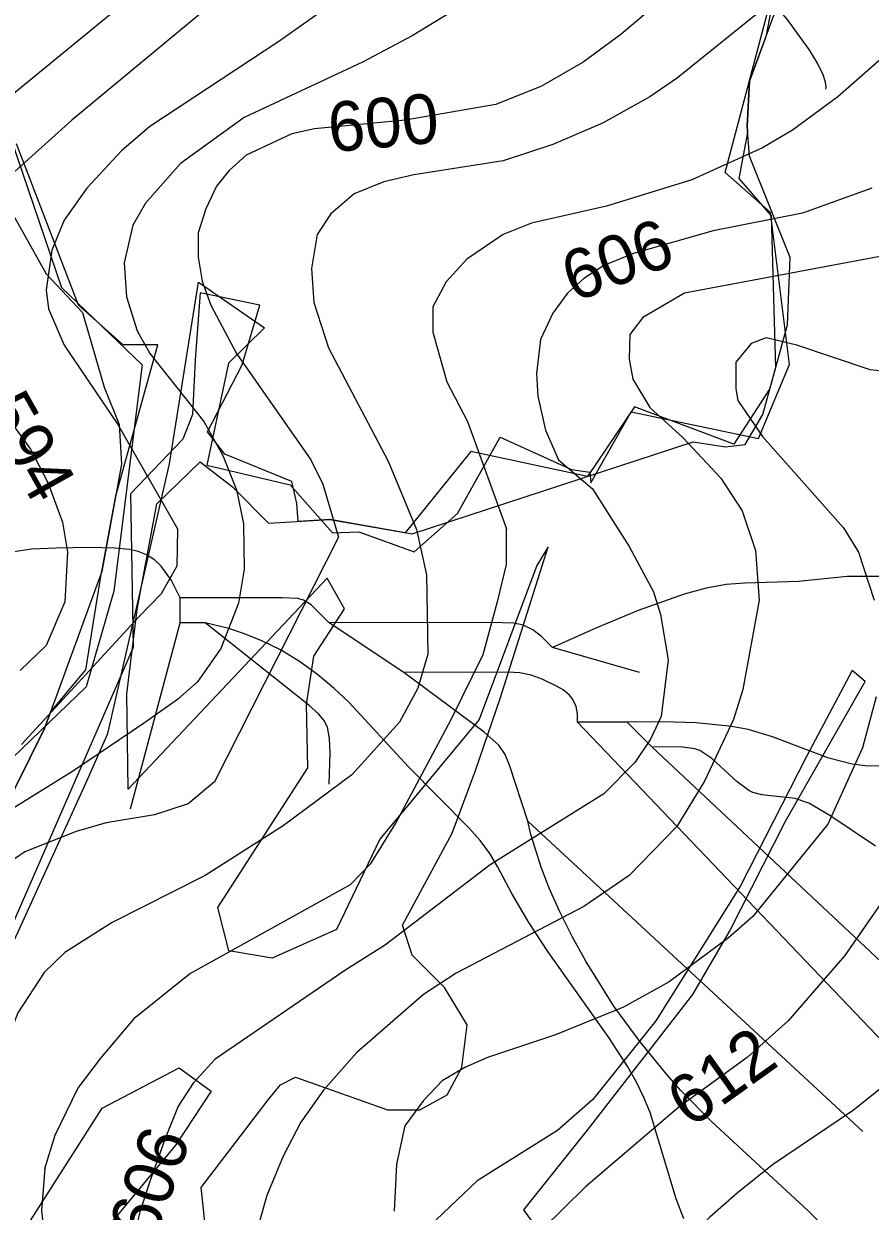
# Model space of a CAD drawing. Extents: x -709584 to -702006, y -1161789 to -1157496.
# Drawn here: x -706843.5 to -706673, y -1159575.6 to -1159336.3 of the extents above; entities that cross this region are included whole.
import ezdxf

# ---------------------------------------------------------------- set-up
doc = ezdxf.new("R2010")
doc.units = 0
for name, color, linetype in [('102_obvod PÚ', 7, 'Continuous'), ('120_vrstevnice hlavní', 7, 'Continuous'), ('121_vrstevnice hlavní_popis', 7, 'Continuous'), ('122_vrstevnice základní', 7, 'Continuous'), ('408_BPEJ_linie', 7, 'Continuous'), ('411_akumulovaný odtok', 7, 'Continuous'), ('419_LPIS PB', 7, 'Continuous')]:
    doc.layers.add(name, color=color, linetype=linetype)

msp = doc.modelspace()

# ---------------------------------------------------------------- linework, layer by layer
at = {"layer": '102_obvod PÚ'}
for points in [[(-706848.95, -1159528.57), (-706830.93, -1159489.21), (-706826.6, -1159479.29), (-706814.16, -1159424.99), (-706808.34, -1159388.37), (-706795.05, -1159397.55), (-706802.3, -1159404.68), (-706806.63, -1159425.27), (-706789.86, -1159429.21), (-706781.31, -1159438.85), (-706776, -1159438.67), (-706764.88, -1159442.72), (-706756.15, -1159434.97), (-706747.54, -1159419.57), (-706733.17, -1159426.13), (-706729.53, -1159426.67), (-706729.3, -1159428.78), (-706721.2, -1159414.52), (-706695.54, -1159419.88), (-706689.26, -1159404.94), (-706693.14, -1159374.31), (-706702.27, -1159366.26), (-706692.33, -1159328.63)], [(-706846.05, -1159359.62), (-706835.89, -1159389.45), (-706819.69, -1159405.02), (-706825.4, -1159450.65), (-706830.93, -1159469.93), (-706862.53, -1159500.28)]]:
    msp.add_lwpolyline(points, dxfattribs=at)
at = {"layer": '120_vrstevnice hlavní'}
for points in [[(-706709.12, -1159326.46), (-706723.26, -1159338.46), (-706730.83, -1159344.03), (-706739.26, -1159348.89), (-706748.41, -1159352.6), (-706766.69, -1159355.75), (-706784.98, -1159357.46), (-706789.55, -1159358.46), (-706798.7, -1159362.75), (-706802.12, -1159365.89), (-706804.7, -1159369.03), (-706806.84, -1159373.6), (-706808.41, -1159378.46), (-706808.41, -1159383.32), (-706807.55, -1159388.18), (-706805.84, -1159393.03), (-706800.7, -1159402.75), (-706785.7, -1159424.18), (-706783.27, -1159429.04), (-706780.12, -1159439.75)], [(-706661.58, -1159407.24), (-706673.06, -1159406.06), (-706687.83, -1159401.03), (-706693.98, -1159399.61), (-706696.98, -1159400.75), (-706700.12, -1159404.46), (-706700.12, -1159409.89), (-706699.69, -1159412.18), (-706694.69, -1159419.46), (-706678.4, -1159437.89), (-706675.4, -1159442.75), (-706672.26, -1159452.47)], [(-706780.12, -1159439.75), (-706805.08, -1159489.03), (-706810.37, -1159493.49), (-706817.21, -1159495.68), (-706826.92, -1159497.3), (-706832.98, -1159499.04), (-706843.27, -1159503.18), (-706853.13, -1159509.9), (-706857.13, -1159513.61), (-706860.56, -1159517.61), (-706864.27, -1159523.33), (-706866.56, -1159528.47), (-706868.13, -1159533.61), (-706872.89, -1159562.85)], [(-706671.83, -1159471.9), (-706674.55, -1159482.18), (-706681.55, -1159497.61), (-706696.69, -1159516.18), (-706701.55, -1159520.47), (-706713.55, -1159529.33), (-706722.69, -1159534.47), (-706736.41, -1159540.04), (-706750.12, -1159544.61), (-706754.69, -1159546.61), (-706759.27, -1159549.33), (-706763.02, -1159553.25), (-706766.78, -1159558.34), (-706768.46, -1159566.12), (-706768.88, -1159575.57)]]:
    msp.add_lwpolyline(points, dxfattribs=at)
msp.add_open_spline([(-706768.88, -1159575.57), (-706768.88, -1159575.58)], degree=1, dxfattribs=at)
at = {"layer": '122_vrstevnice základní'}
for points in [[(-706654.69, -1159145.74), (-706680.12, -1159166.88), (-706687.41, -1159173.59), (-706720.55, -1159207.17), (-706736.55, -1159225.17), (-706751.84, -1159244.46), (-706792.84, -1159298.46), (-706808.7, -1159317.6), (-706826.27, -1159334.6), (-706862.27, -1159364.03)], [(-706643.12, -1159157.45), (-706668.12, -1159182.59), (-706699.41, -1159216.6), (-706708.83, -1159228.74), (-706766.12, -1159293.46), (-706792.27, -1159320.32), (-706807.98, -1159334.32), (-706833.84, -1159355.75), (-706845.27, -1159366.03)], [(-706622.69, -1159158.74), (-706651.26, -1159189.31), (-706674.4, -1159215.17), (-706689.69, -1159233.74), (-706698.83, -1159246.31), (-706715.26, -1159266.74), (-706752.84, -1159307.31), (-706761.84, -1159316.17), (-706777.27, -1159329.32), (-706792.12, -1159339.89), (-706818.12, -1159357.03), (-706823.84, -1159361.89), (-706830.84, -1159369.46), (-706835.41, -1159375.89), (-706837.84, -1159381.89), (-706838.98, -1159389.89), (-706838.56, -1159393.75), (-706835.41, -1159401.03), (-706824.55, -1159417.03), (-706812.55, -1159438.04), (-706812.7, -1159445.61), (-706815.84, -1159451.18), (-706820.41, -1159455.89), (-706843.94, -1159481.51)], [(-706590.33, -1159211.59), (-706594.67, -1159221.73), (-706609.26, -1159257.6), (-706614.97, -1159269.6), (-706620.54, -1159279.31), (-706635.83, -1159302.6), (-706648.12, -1159318.17), (-706662.55, -1159335.03), (-706671.26, -1159343.75), (-706679.55, -1159351.03), (-706688.69, -1159357.75), (-706694.69, -1159361.32), (-706708.98, -1159367.75), (-706726.12, -1159373.03), (-706741.26, -1159376.46), (-706746.98, -1159378.75), (-706754.27, -1159383.75), (-706758.41, -1159388.32), (-706761.12, -1159393.32), (-706761.12, -1159398.46), (-706758.27, -1159408.46), (-706754.12, -1159416.46), (-706746.27, -1159438.04)], [(-706690.83, -1159330.17), (-706711.83, -1159347.17), (-706717.41, -1159351.03), (-706726.98, -1159356.32), (-706736.98, -1159360.6), (-706746.98, -1159363.89), (-706764.98, -1159366.75), (-706770.98, -1159368.18), (-706776.98, -1159370.6), (-706781.7, -1159374.6), (-706784.41, -1159378.75), (-706785.55, -1159385.61), (-706785.12, -1159392.46), (-706782.12, -1159401.61), (-706770.12, -1159424.46), (-706764.41, -1159438.18), (-706762.41, -1159447.32), (-706762.12, -1159463.32), (-706764.12, -1159470.18), (-706767.84, -1159477.04), (-706777.41, -1159487.61), (-706791.27, -1159497.9), (-706806.98, -1159507.9), (-706825.71, -1159517.41)], [(-706755.69, -1159332.89), (-706765.27, -1159338.75), (-706775.27, -1159344.03), (-706799.12, -1159355.18), (-706811.98, -1159364.46), (-706818.98, -1159372.46), (-706821.55, -1159376.89), (-706823.27, -1159384.46), (-706822.84, -1159391.32), (-706820.7, -1159398.18), (-706818.12, -1159402.75), (-706807.27, -1159416.46), (-706803.41, -1159423.32), (-706800.7, -1159430.18), (-706799.27, -1159437.04), (-706799.12, -1159446.18), (-706800.27, -1159453.04), (-706803.84, -1159462.18), (-706808.55, -1159468.89), (-706812.55, -1159472.47), (-706819.41, -1159477.32), (-706833.51, -1159486.8), (-706848.84, -1159496.32)], [(-706672.69, -1159369.46), (-706686.69, -1159374.46), (-706704.69, -1159378.03), (-706720.69, -1159382.6), (-706726.69, -1159385.03), (-706730.69, -1159387.61), (-706733.98, -1159390.61), (-706736.98, -1159394.61), (-706739.41, -1159399.89), (-706740.26, -1159406.75), (-706739.98, -1159411.32), (-706738.41, -1159418.18), (-706735.83, -1159424.18), (-706728.98, -1159430.03), (-706721.55, -1159441.61), (-706716.69, -1159450.75), (-706715.26, -1159455.32), (-706713.69, -1159464.47), (-706715.12, -1159475.9), (-706717.26, -1159480.47), (-706720.41, -1159485.18), (-706726.69, -1159491.47), (-706749.55, -1159505.75), (-706770.69, -1159521.9), (-706778.84, -1159527.04)], [(-706664.98, -1159382.03), (-706710.41, -1159390.61), (-706718.83, -1159395.46), (-706721.41, -1159398.89), (-706721.55, -1159403.89), (-706720.83, -1159407.89), (-706717.41, -1159413.61), (-706710.69, -1159419.75), (-706703.12, -1159427.89), (-706698.83, -1159434.46), (-706696.12, -1159442.47), (-706695.41, -1159452.47), (-706698.69, -1159470.47), (-706700.55, -1159476.47), (-706706.41, -1159488.9), (-706711.98, -1159498.04), (-706721.55, -1159507.9), (-706730.69, -1159514.18), (-706756.41, -1159527.61), (-706762.98, -1159531.9), (-706776.41, -1159543.61), (-706783.12, -1159551.18), (-706787.7, -1159557.61), (-706791.26, -1159564.49), (-706794.58, -1159572.43)], [(-706855.98, -1159403.03), (-706842.13, -1159422.03), (-706838.7, -1159428.75), (-706835.7, -1159436.75), (-706834.7, -1159442.75), (-706835.27, -1159452.75), (-706838.98, -1159461.61), (-706844.27, -1159466.61)], [(-706839.29, -1159566.96), (-706837.19, -1159560.26), (-706832.63, -1159550.81), (-706827.98, -1159544.76), (-706820.98, -1159536.47), (-706810.12, -1159527.75), (-706777.7, -1159509.75), (-706773.57, -1159505.47), (-706768.56, -1159497.39), (-706757.41, -1159476.48), (-706751, -1159463.38), (-706747.93, -1159452.23), (-706746.26, -1159445.26), (-706746.27, -1159438.04)], [(-706619.55, -1159445.89), (-706624.59, -1159454.52), (-706628.86, -1159465.05), (-706631.5, -1159477.96), (-706633.14, -1159491.38), (-706635.55, -1159502.75), (-706641.12, -1159516.75), (-706645.83, -1159525.04), (-706654.26, -1159536.18), (-706662.4, -1159544.04), (-706676.4, -1159555.18), (-706692.69, -1159566.19), (-706699.83, -1159571.9), (-706705.34, -1159576.78), (-706711.29, -1159582.62)], [(-706656.12, -1159449.89), (-706654.69, -1159462.75), (-706654.83, -1159471.9), (-706656.12, -1159481.04), (-706659.55, -1159492.47), (-706668.12, -1159509.61), (-706678.12, -1159524.04), (-706689.55, -1159537.18), (-706697.83, -1159544.61), (-706711.55, -1159554.61), (-706730.35, -1159570.68), (-706739.13, -1159579.22)], [(-706825.71, -1159517.41), (-706835.27, -1159523.47), (-706839.41, -1159527.47), (-706844.7, -1159535.61), (-706847.98, -1159544.18), (-706849.27, -1159552.76), (-706849.81, -1159565.68)], [(-706778.84, -1159527.04), (-706804.98, -1159544.9), (-706809.41, -1159549.76), (-706812.43, -1159554.39), (-706815.04, -1159560.91), (-706818.13, -1159569.55)], [(-706839.29, -1159566.96), (-706839.92, -1159575.4), (-706837.18, -1159601.02), (-706859.16, -1159631.68)], [(-706818.13, -1159569.55), (-706820.06, -1159575.49), (-706824.32, -1159592.45)], [(-706794.58, -1159572.43), (-706796.07, -1159577.85), (-706797.41, -1159586.38), (-706798.12, -1159608.68), (-706798.7, -1159622.57), (-706799.57, -1159630.23), (-706855.11, -1159702.56)]]:
    msp.add_lwpolyline(points, dxfattribs=at)
for points in [[(-706839.29, -1159566.96), (-706839.29, -1159566.96)], [(-706818.13, -1159569.55), (-706818.13, -1159569.55)], [(-706794.58, -1159572.43), (-706794.58, -1159572.43)]]:
    msp.add_open_spline(points, degree=1, dxfattribs=at)
at = {"layer": '408_BPEJ_linie'}
for points in [[(-706688.5, -1159310), (-706694.04, -1159338.95), (-706697.33, -1159347.89), (-706697.83, -1159356.93), (-706697.73, -1159358.23), (-706699.5, -1159367.5), (-706693, -1159375), (-706692.07, -1159405.61), (-706693.28, -1159409.95), (-706700.5, -1159421), (-706720.5, -1159413.5), (-706730, -1159427.5), (-706753.5, -1159422.5), (-706766.68, -1159438.86), (-706781.9, -1159436.2), (-706788.23, -1159436.56), (-706788.5, -1159433), (-706789.5, -1159428.5), (-706803, -1159423), (-706806.5, -1159418.5), (-706799.5, -1159405), (-706796, -1159393), (-706808, -1159390.5), (-706809, -1159404), (-706809.5, -1159415), (-706811.5, -1159420), (-706822, -1159431), (-706821.5, -1159462), (-706849, -1159525)], [(-706848.35, -1159496.37), (-706839.34, -1159478.29), (-706838.13, -1159474.98), (-706831, -1159466.5), (-706827.87, -1159446.78), (-706827.82, -1159446.66), (-706825, -1159431.41), (-706816.5, -1159401), (-706823.5, -1159401), (-706832.5, -1159393), (-706845, -1159360.5)]]:
    msp.add_lwpolyline(points, dxfattribs=at)
at = {"layer": '411_akumulovaný odtok'}
for p, q in [((-706811.99, -1159457), (-706811.99, -1159452)), ((-706821.99, -1159494.5), (-706811.99, -1159457)), ((-706806.99, -1159457), (-706811.99, -1159457)), ((-706766.99, -1159467), (-706781.99, -1159457)), ((-706719.49, -1159467), (-706736.99, -1159462)), ((-706721.99, -1159477), (-706731.99, -1159477)), ((-706716.99, -1159482), (-706721.99, -1159477)), ((-706674.49, -1159559.5), (-706741.99, -1159497))]:
    msp.add_line(p, q, dxfattribs=at)
for points in [[(-706681.99, -1159349.5), (-706681.87, -1159349.08), (-706682.04, -1159348.07), (-706682.53, -1159346.59), (-706683.65, -1159344.24), (-706685.3, -1159341.5), (-706689.75, -1159335.4), (-706694.89, -1159329.34), (-706701.85, -1159322.11), (-706759.36, -1159264.71), (-706768.21, -1159255.54), (-706773.08, -1159249.46), (-706775.38, -1159246.13), (-706777.41, -1159242.77), (-706780.01, -1159237.5), (-706781.54, -1159233.57), (-706781.99, -1159232)], [(-706811.99, -1159452), (-706813.74, -1159448.47), (-706815.85, -1159445.59), (-706817.19, -1159444.33), (-706818.78, -1159443.31), (-706820.46, -1159442.61), (-706822.13, -1159442.21), (-706825.34, -1159441.95), (-706830.29, -1159441.86), (-706836.97, -1159441.94), (-706841.94, -1159442.19), (-706846.79, -1159442.88), (-706855.63, -1159445.46), (-706858.64, -1159445.68), (-706861.75, -1159445.26), (-706866.46, -1159444.03), (-706886.99, -1159437)], [(-706670.53, -1159447.68), (-706677.65, -1159447.65), (-706687.48, -1159448.68), (-706698.31, -1159448.99), (-706702.01, -1159449.26), (-706706.05, -1159450.02), (-706710.48, -1159451.24), (-706719.76, -1159454.53), (-706728.3, -1159458.09), (-706736.99, -1159462)], [(-706781.99, -1159457), (-706785.63, -1159453.37), (-706787.16, -1159452.42), (-706788.32, -1159452.13), (-706791.45, -1159451.96), (-706811.99, -1159452)], [(-706781.99, -1159489.5), (-706781.82, -1159483.18), (-706781.91, -1159480.3), (-706782.34, -1159478.01), (-706783.05, -1159476.63), (-706784.14, -1159475.37), (-706786.08, -1159473.63), (-706806.99, -1159457)], [(-706710.59, -1159577.13), (-706712.08, -1159573.09), (-706717.37, -1159555.71), (-706718.6, -1159552.67), (-706720.13, -1159549.54), (-706721.86, -1159546.5), (-706725.67, -1159540.57), (-706737.93, -1159523.21), (-706741.78, -1159517.4), (-706745.23, -1159511.54), (-706748.08, -1159506.09), (-706749.65, -1159503.49), (-706751.62, -1159500.85), (-706753.85, -1159498.34), (-706766.05, -1159486.06), (-706778.01, -1159473.01), (-706780.98, -1159470.21), (-706784.35, -1159467.4), (-706788, -1159464.77), (-706791.82, -1159462.46), (-706795.54, -1159460.64), (-706799.07, -1159459.22), (-706802.19, -1159458.17), (-706806.99, -1159457)], [(-706736.99, -1159462), (-706739.23, -1159459.76), (-706740.97, -1159458.44), (-706742.93, -1159457.48), (-706744.82, -1159457.1), (-706749.41, -1159456.96), (-706781.99, -1159457)], [(-706731.99, -1159477), (-706731.99, -1159475.36), (-706732.27, -1159473.86), (-706733, -1159472.3), (-706733.57, -1159471.6), (-706734.88, -1159470.53), (-706736.24, -1159469.77), (-706739.09, -1159468.38), (-706741.29, -1159467.54), (-706743.61, -1159467.09), (-706746, -1159466.96), (-706766.99, -1159467)], [(-706741.99, -1159497), (-706745.67, -1159485.71), (-706746.58, -1159483.57), (-706747.84, -1159481.67), (-706750.8, -1159479.06), (-706766.99, -1159467)], [(-706579.49, -1159629.5), (-706583.27, -1159624.18), (-706589.17, -1159616.82), (-706592.75, -1159612.79), (-706596.59, -1159608.78), (-706600.53, -1159604.99), (-706604.42, -1159601.59), (-706608.08, -1159598.79), (-706617.81, -1159592.6), (-706620.99, -1159590.44), (-706624.32, -1159587.9), (-706630.69, -1159582.34), (-706636.82, -1159576.42), (-706648.8, -1159564.13), (-706731.99, -1159477)], [(-706589.49, -1159499.5), (-706603.81, -1159491.42), (-706612.59, -1159486.87), (-706617.42, -1159484.86), (-706619.83, -1159484.08), (-706622.29, -1159483.5), (-706624.92, -1159483.14), (-706627.58, -1159482.99), (-706633, -1159483.07), (-706641.22, -1159483.69), (-706663.23, -1159485.73), (-706668.68, -1159485.97), (-706674.05, -1159485.81), (-706676.69, -1159485.46), (-706681.33, -1159484.28), (-706692.71, -1159479.99), (-706697.59, -1159478.5), (-706700.88, -1159477.89), (-706708.06, -1159477.19), (-706714.88, -1159476.96), (-706721.99, -1159477)], [(-706671.99, -1159502), (-706681.13, -1159495.8), (-706685.4, -1159493.34), (-706688.13, -1159492.44), (-706694.87, -1159491.69), (-706696.66, -1159491.19), (-706697.5, -1159490.78), (-706699.82, -1159489.08), (-706704.93, -1159484.36), (-706707.32, -1159482.76), (-706708.33, -1159482.43), (-706710.76, -1159482.04), (-706716.99, -1159482)], [(-706524.49, -1159674.5), (-706525.18, -1159673.85), (-706526.52, -1159671.64), (-706533.03, -1159658.66), (-706535.98, -1159653.09), (-706539.31, -1159647.41), (-706542.91, -1159641.82), (-706546.62, -1159636.5), (-706550.27, -1159631.66), (-706556.98, -1159623.59), (-706563.82, -1159615.99), (-706571.08, -1159608.51), (-706578.73, -1159601.16), (-706590.47, -1159590.41), (-706602.37, -1159580.03), (-706610.42, -1159573.47), (-706618.62, -1159567.48), (-706622.8, -1159564.81), (-706630.76, -1159560.32), (-706634.59, -1159557.94), (-706638.65, -1159554.87), (-706642.57, -1159551.49), (-706657.95, -1159537.41), (-706716.99, -1159482)], [(-706679.31, -1159581.67), (-706685.54, -1159575.5), (-706704.98, -1159557.52), (-706711.16, -1159551.25), (-706714, -1159548.05), (-706719.39, -1159541.42), (-706724.65, -1159534.24), (-706730.32, -1159525.16), (-706733.06, -1159520.23), (-706735.55, -1159515.27), (-706737.69, -1159510.48), (-706739.32, -1159506.23), (-706741.41, -1159499.63), (-706741.99, -1159497)]]:
    msp.add_lwpolyline(points, dxfattribs=at)
at = {"layer": '419_LPIS PB'}
for points in [[(-706806.9, -1159578.9), (-706807.79, -1159570.82), (-706794.29, -1159553.11), (-706791.79, -1159550.09), (-706788.78, -1159548.59), (-706770.26, -1159555.11), (-706763.75, -1159555.11), (-706758.25, -1159552.1), (-706755.25, -1159546.58), (-706754.24, -1159538.04), (-706758.75, -1159530.51), (-706765.26, -1159523.98), (-706767.26, -1159517.96), (-706757.25, -1159499.38), (-706752.52, -1159486.75), (-706747.58, -1159472.28), (-706737.92, -1159441.67), (-706740.17, -1159445.47), (-706751.81, -1159476.52), (-706761.6, -1159488.3), (-706771.8, -1159500.6), (-706780.5, -1159518.8), (-706793.5, -1159524.6), (-706802.2, -1159523.1), (-706804.4, -1159514.4), (-706786.3, -1159486.2), (-706786.57, -1159473.45), (-706785.09, -1159463.7), (-706778.94, -1159454.22), (-706782.38, -1159447.99), (-706822.5, -1159490.5), (-706822.76, -1159471.34), (-706820.66, -1159454.3), (-706816.71, -1159433.01), (-706808, -1159424.6), (-706801.5, -1159429.6), (-706794.2, -1159436.9), (-706781.9, -1159436.2), (-706765.3, -1159439.1), (-706708.7, -1159420.55), (-706702.19, -1159421.55), (-706698.18, -1159421.05), (-706694.68, -1159415.02), (-706689.67, -1159396.95), (-706689.17, -1159383.39), (-706697.33, -1159362.96), (-706697.83, -1159356.93), (-706697.33, -1159347.89), (-706680.32, -1159301.7)], [(-706846.6, -1159373.1), (-706839, -1159386.7), (-706831.7, -1159394.5), (-706827.32, -1159409.5), (-706824.32, -1159417.03), (-706823.82, -1159425.07), (-706827.82, -1159446.66), (-706839.34, -1159478.29), (-706848.35, -1159496.37)], [(-706739.17, -1159580.35), (-706742.8, -1159575.28), (-706730.22, -1159559.55), (-706708.77, -1159531.9), (-706701.36, -1159519.2), (-706690.07, -1159496.98), (-706674.05, -1159468.8), (-706676.67, -1159466.64), (-706685.84, -1159483.93), (-706699.18, -1159509.98), (-706716.18, -1159537.2), (-706728.88, -1159553.07), (-706735.98, -1159559.32), (-706752.22, -1159569.48), (-706765.98, -1159582.52)], [(-706843.1, -1159578.9), (-706827.7, -1159554.8), (-706812.2, -1159546.7), (-706805.8, -1159551.4), (-706812.9, -1159562.2), (-706829, -1159581.6)]]:
    msp.add_lwpolyline(points, dxfattribs=at)

# ---------------------------------------------------------------- texts
at = {"layer": '121_vrstevnice hlavní_popis'}
for s, rotation, p in [('600', 5.3034, (-706781.78, -1159362.22)), ('606', 20.8343, (-706732.68, -1159392.48)), ('594', 299.3806, (-706852.31, -1159414.1)), ('612', 35.5646, (-706709.22, -1159559)), ('606', 70.7639, (-706817.2, -1159582.05))]:
    msp.add_text(s, height=10, rotation=rotation, dxfattribs=at).set_placement(p)

doc.saveas('drawing.dxf')
